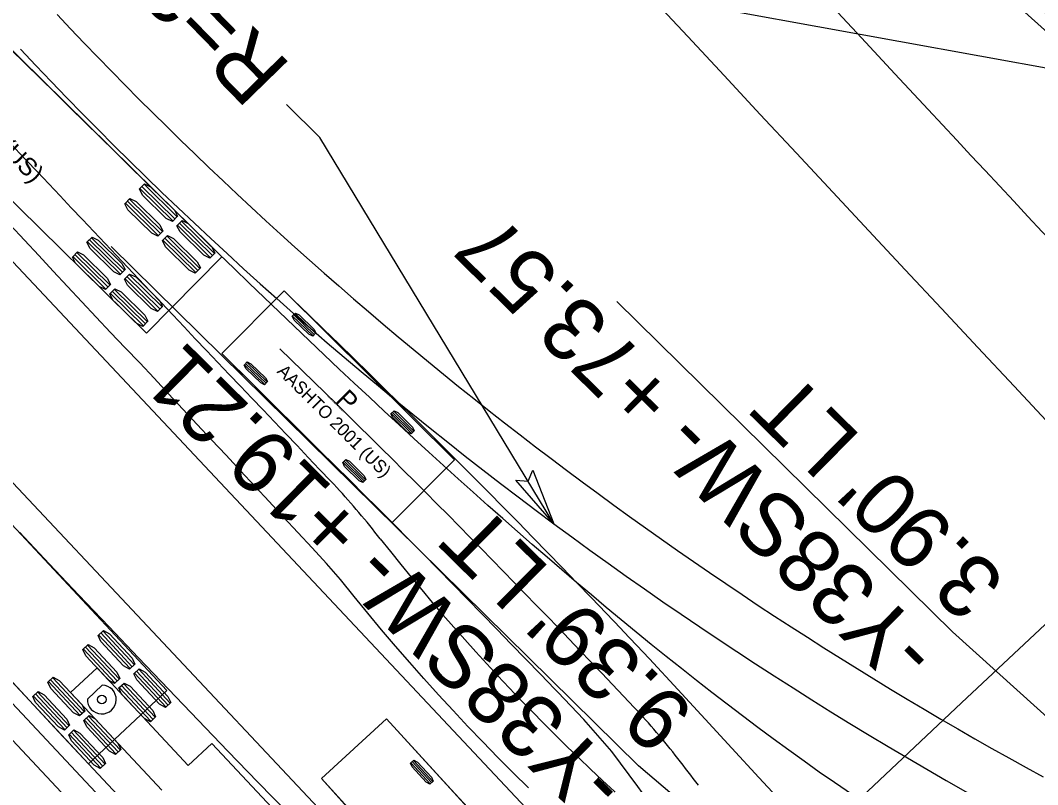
# Model space of a CAD drawing. Extents: x 1262642 to 1268358, y 767825 to 773481.
# Drawn here: x 1266608.5 to 1266689.1, y 772167.3 to 772227.9 of the extents above; entities that cross this region are included whole.
import ezdxf

# ---------------------------------------------------------------- set-up
doc = ezdxf.new("R2010")
doc.units = 0
for name, color, linetype in [('Prop Conc 2ft 6in Curb and Gutter', 7, 'Continuous'), ('Prop Conc 5in Monolithic Keyed In Island', 7, 'Continuous'), ('Prop Dimension', 7, 'Continuous'), ('Prop Dimension Text', 7, 'Continuous'), ('Prop EOT', 7, 'Continuous'), ('Prop Horizontal Alignment', 7, 'Continuous'), ('Prop Horizontal Alignment Station Label', 7, 'Continuous'), ('Prop Lane Lines', 7, 'Continuous'), ('Prop Paved Shoulder', 7, 'Continuous'), ('Prop Shade Light', 7, 'Continuous'), ('Prop Shade Medium', 7, 'Continuous'), ('Prop Terminator CELL', 7, 'Continuous'), ('Scratch_Level_3', 7, 'Continuous')]:
    doc.layers.add(name, color=color, linetype=linetype)

msp = doc.modelspace()

# ---------------------------------------------------------------- linework, layer by layer
at = {"layer": 'Prop Conc 2ft 6in Curb and Gutter'}
msp.add_line((1266506.171, 772278.961), (1266647.877, 772128.235), dxfattribs=at)
at = {"layer": 'Prop Conc 5in Monolithic Keyed In Island'}
for radius, start, end in [(11410.25, 222.8296601, 223.2792706), (11414.25, 222.8297896, 223.4298287)]:
    msp.add_arc((1275047.307, 780021.225), radius, start, end, dxfattribs=at)
at = {"layer": 'Prop Dimension'}
for p, q in [((1266650.81, 772187.946), (1266632.249, 772218.583)), ((1266731.744, 772134.821), (1266682.387, 772179.383)), ((1266684.313, 772146.162), (1266657.504, 772168.739))]:
    msp.add_line(p, q, dxfattribs=at)
at = {"layer": 'Prop Dimension Text'}
for p, q in [((1266755.582, 772212.148), (1266643.887, 772232.407)), ((1266632.249, 772218.583), (1266629.609, 772221.184)), ((1266657.52, 772168.758), (1266615.723, 772209.94)), ((1266682.387, 772179.383), (1266655.806, 772205.574))]:
    msp.add_line(p, q, dxfattribs=at)
at = {"layer": 'Prop EOT'}
msp.add_line((1266507.71, 772280.244), (1266649.334, 772129.605), dxfattribs=at)
for centre, radius, start, end in [((1275047.307, 780021.225), 11439, 220.5050908, 222.9935866), ((1275047.307, 780021.225), 11409.5, 222.8296601, 223.2792706), ((1275047.307, 780021.225), 11415, 222.8297896, 223.4298287), ((1266840.27, 772443.458), 318.091, 223.23333, 243.65317), ((1275047.307, 780021.225), 11439, 222.9935866, 223.2588472)]:
    msp.add_arc(centre, radius, start, end, dxfattribs=at)
at = {"layer": 'Prop Horizontal Alignment'}
msp.add_line((1266456.698, 772369.54), (1266660.642, 772152.615), dxfattribs=at)
at = {"layer": 'Prop Horizontal Alignment Station Label'}
for p, q in [((1266683.114, 772173.743), (1266860.999, 772340.982)), ((1266769.823, 772154.715), (1266566.881, 772338.064)), ((1266661.735, 772153.643), (1266683.114, 772173.743))]:
    msp.add_line(p, q, dxfattribs=at)
at = {"layer": 'Prop Lane Lines'}
msp.add_line((1266516.453, 772288.464), (1266651.899, 772144.396), dxfattribs=at)
for radius, start, end in [(11427, 216.3674993, 223.5476842), (11415, 220.9464115, 223.1041206)]:
    msp.add_arc((1275047.307, 780021.225), radius, start, end, dxfattribs=at)
at = {"layer": 'Prop Paved Shoulder'}
for centre, radius, start, end in [((1275047.307, 780021.225), 11449, 220.5050908, 223.2024475), ((1266840.27, 772443.458), 314.091, 223.23333, 241.33253)]:
    msp.add_arc(centre, radius, start, end, dxfattribs=at)
at = {"layer": 'Prop Shade Light'}
for centre, radius, start, end in [((1275047.307, 780021.225), 11439, 220.5050908, 222.9935866), ((1275047.307, 780021.225), 11449, 220.5050908, 223.2024475), ((1266840.27, 772443.458), 314.091, 223.23333, 241.33253), ((1266840.27, 772443.458), 318.091, 223.23333, 243.65317), ((1275047.307, 780021.225), 11439, 222.9935866, 223.2588472)]:
    msp.add_arc(centre, radius, start, end, dxfattribs=at)
at = {"layer": 'Prop Shade Medium'}
for radius, start, end in [(11410.25, 222.8296601, 223.2792706), (11414.25, 222.8297896, 223.4298287)]:
    msp.add_arc((1275047.307, 780021.225), radius, start, end, dxfattribs=at)
at = {"layer": 'Prop Terminator CELL'}
msp.add_lwpolyline([(1266649.141, 772192.197), (1266650.81, 772187.946), (1266647.781, 772191.402), (1266648.763, 772191.325)], close=True, dxfattribs=at)
at = {"layer": 'Scratch_Level_3'}
for p, q in [((1266624.483, 772209.122), (1266590.256, 772242.775)), ((1266584.297, 772236.714), (1266618.524, 772203.061)), ((1266618.321, 772214.86), (1266620.935, 772212.289)), ((1266617.999, 772214.533), (1266620.614, 772211.962)), ((1266618.16, 772214.696), (1266620.775, 772212.126)), ((1266616.843, 772213.357), (1266619.457, 772210.786)), ((1266617.003, 772213.52), (1266619.618, 772210.949)), ((1266617.164, 772213.683), (1266619.779, 772211.113)), ((1266620.971, 772211.612), (1266623.585, 772209.041)), ((1266621.131, 772211.775), (1266623.746, 772209.205)), ((1266621.292, 772211.939), (1266623.906, 772209.368)), ((1266620.135, 772210.762), (1266622.75, 772208.191)), ((1266613.84, 772210.302), (1266616.454, 772207.732)), ((1266614, 772210.466), (1266616.615, 772207.895)), ((1266614.161, 772210.629), (1266616.776, 772208.058)), ((1266619.814, 772210.435), (1266622.428, 772207.865)), ((1266619.974, 772210.599), (1266622.589, 772208.028)), ((1266620.129, 772174.722), (1266587.354, 772209.79)), ((1266612.683, 772209.126), (1266615.297, 772206.555)), ((1266612.843, 772209.289), (1266615.458, 772206.718)), ((1266613.004, 772209.452), (1266615.619, 772206.882)), ((1266618.524, 772203.061), (1266624.483, 772209.122)), ((1266616.971, 772207.544), (1266619.586, 772204.974)), ((1266617.132, 772207.708), (1266619.747, 772205.137)), ((1266616.811, 772207.381), (1266619.425, 772204.81)), ((1266615.654, 772206.204), (1266618.268, 772203.634)), ((1266615.815, 772206.368), (1266618.429, 772203.797)), ((1266615.975, 772206.531), (1266618.59, 772203.961)), ((1266629.43, 772206.402), (1266624.5, 772201.433)), ((1266642.918, 772193.02), (1266629.43, 772206.402)), ((1266630.101, 772204.418), (1266631.718, 772202.854)), ((1266630.199, 772204.519), (1266631.816, 772202.955)), ((1266630.296, 772204.62), (1266631.913, 772203.056)), ((1266581.144, 772203.986), (1266613.919, 772168.918)), ((1266624.5, 772201.433), (1266637.988, 772188.051)), ((1266624.5, 772201.433), (1266624.5, 772201.433)), ((1266626.276, 772200.553), (1266627.893, 772198.989)), ((1266626.374, 772200.654), (1266627.991, 772199.09)), ((1266626.472, 772200.755), (1266628.089, 772199.191)), ((1266637.921, 772196.679), (1266639.518, 772195.095)), ((1266638.02, 772196.779), (1266639.617, 772195.194)), ((1266638.119, 772196.879), (1266639.716, 772195.294)), ((1266634.289, 772193.019), (1266635.886, 772191.434)), ((1266637.988, 772188.051), (1266642.918, 772193.02)), ((1266634.091, 772192.819), (1266635.688, 772191.235)), ((1266634.19, 772192.919), (1266635.787, 772191.334)), ((1266617.392, 772176.612), (1266614.888, 772179.291)), ((1266617.559, 772176.769), (1266615.056, 772179.448)), ((1266617.225, 772176.456), (1266614.721, 772179.135)), ((1266616.019, 772175.329), (1266613.515, 772178.008)), ((1266616.187, 772175.486), (1266613.683, 772178.165)), ((1266616.354, 772175.642), (1266613.85, 772178.321)), ((1266614.6, 772176.512), (1266612.505, 772174.555)), ((1266621.826, 772168.78), (1266614.6, 772176.512)), ((1266620.07, 772173.412), (1266617.566, 772176.091)), ((1266620.237, 772173.568), (1266617.733, 772176.247)), ((1266620.405, 772173.725), (1266617.901, 772176.404)), ((1266613.255, 772172.746), (1266610.751, 772175.425)), ((1266613.422, 772172.902), (1266610.919, 772175.581)), ((1266613.59, 772173.059), (1266611.086, 772175.738)), ((1266619.199, 772172.598), (1266616.695, 772175.277)), ((1266612.217, 772171.776), (1266609.713, 772174.455)), ((1266612.384, 772171.932), (1266609.881, 772174.611)), ((1266612.505, 772174.555), (1266619.732, 772166.823)), ((1266615.014, 772175.154), (1266613.833, 772174.05)), ((1266613.919, 772168.918), (1266620.129, 772174.722)), ((1266618.864, 772172.285), (1266616.361, 772174.964)), ((1266619.032, 772172.442), (1266616.528, 772175.12)), ((1266620.129, 772174.722), (1266620.129, 772174.722)), ((1266612.05, 772171.619), (1266609.546, 772174.298)), ((1266616.1, 772169.702), (1266613.596, 772172.381)), ((1266616.268, 772169.858), (1266613.764, 772172.537)), ((1266616.435, 772170.015), (1266613.931, 772172.694)), ((1266637.54, 772172.472), (1266632.375, 772167.748)), ((1266650.364, 772158.453), (1266637.54, 772172.472)), ((1266614.895, 772168.575), (1266612.391, 772171.254)), ((1266615.062, 772168.732), (1266612.558, 772171.41)), ((1266615.229, 772168.888), (1266612.726, 772171.567)), ((1266623.701, 772170.533), (1266621.826, 772168.78)), ((1266633.944, 772159.574), (1266623.701, 772170.533)), ((1266640.994, 772167.331), (1266639.475, 772168.991)), ((1266641.098, 772167.426), (1266639.579, 772169.086)), ((1266641.201, 772167.521), (1266639.683, 772169.181)), ((1266632.375, 772167.748), (1266645.199, 772153.728))]:
    msp.add_line(p, q, dxfattribs=at)
for points in [[(1266673.036, 772167.425), (1266671.84, 772168.26), (1266670.632, 772169.117), (1266669.415, 772169.995), (1266668.189, 772170.89), (1266666.966, 772171.797), (1266665.748, 772172.713), (1266664.533, 772173.637), (1266663.323, 772174.57), (1266662.117, 772175.511), (1266660.915, 772176.46), (1266659.717, 772177.416), (1266658.523, 772178.379), (1266657.332, 772179.349), (1266656.146, 772180.326), (1266654.962, 772181.309), (1266653.783, 772182.298), (1266652.606, 772183.293), (1266651.433, 772184.293), (1266650.264, 772185.299), (1266649.096, 772186.311), (1266647.926, 772187.333), (1266646.754, 772188.364), (1266645.579, 772189.404), (1266644.404, 772190.453), (1266643.23, 772191.507), (1266642.057, 772192.567), (1266640.885, 772193.633), (1266639.714, 772194.703), (1266638.544, 772195.78), (1266637.366, 772196.869), (1266636.18, 772197.973), (1266634.986, 772199.09), (1266633.79, 772200.213), (1266632.596, 772201.341), (1266631.404, 772202.472), (1266630.213, 772203.607), (1266629.023, 772204.746), (1266627.836, 772205.888), (1266626.649, 772207.033), (1266625.465, 772208.181), (1266624.282, 772209.333), (1266623.1, 772210.487), (1266621.92, 772211.643), (1266620.741, 772212.802), (1266619.561, 772213.962), (1266618.381, 772215.122), (1266617.201, 772216.282), (1266616.021, 772217.443), (1266614.84, 772218.604), (1266613.658, 772219.766), (1266612.477, 772220.927), (1266611.295, 772222.089), (1266610.113, 772223.252), (1266608.93, 772224.414), (1266607.747, 772225.577)], [(1266648.799, 772167.005), (1266647.579, 772168.207), (1266646.37, 772169.42), (1266645.174, 772170.646), (1266643.99, 772171.883), (1266642.818, 772173.132), (1266641.658, 772174.392), (1266640.511, 772175.663), (1266639.377, 772176.946), (1266638.255, 772178.24), (1266637.145, 772179.545), (1266636.049, 772180.86), (1266634.966, 772182.187), (1266633.896, 772183.524), (1266632.792, 772184.803), (1266631.655, 772186.029), (1266630.52, 772187.252), (1266629.382, 772188.476), (1266628.241, 772189.701), (1266627.1, 772190.926), (1266625.96, 772192.149), (1266624.82, 772193.372), (1266623.68, 772194.594), (1266622.54, 772195.816), (1266621.4, 772197.037), (1266620.261, 772198.258), (1266619.121, 772199.478), (1266617.982, 772200.698), (1266616.815, 772201.884), (1266615.677, 772203.105), (1266614.539, 772204.325), (1266613.4, 772205.545), (1266612.262, 772206.764), (1266611.124, 772207.984), (1266609.985, 772209.203), (1266608.847, 772210.422), (1266607.709, 772211.641)], [(1266656.331, 772179.411), (1266656.1, 772179.653), (1266654.945, 772180.86), (1266653.787, 772182.066), (1266652.627, 772183.269), (1266651.464, 772184.47), (1266650.3, 772185.669), (1266649.133, 772186.866), (1266647.963, 772188.06), (1266646.792, 772189.252), (1266645.618, 772190.442), (1266644.442, 772191.63), (1266643.263, 772192.815), (1266642.083, 772193.998), (1266640.9, 772195.179), (1266639.715, 772196.358), (1266638.527, 772197.535), (1266637.338, 772198.709), (1266636.146, 772199.881), (1266634.952, 772201.051), (1266633.755, 772202.218), (1266632.557, 772203.383), (1266631.356, 772204.546), (1266630.153, 772205.707), (1266629.43, 772206.402)], [(1266651.109, 772174.581), (1266650.88, 772174.821), (1266649.734, 772176.019), (1266648.585, 772177.214), (1266647.433, 772178.408), (1266646.28, 772179.599), (1266645.124, 772180.788), (1266643.966, 772181.975), (1266642.806, 772183.159), (1266641.644, 772184.342), (1266640.479, 772185.522), (1266639.312, 772186.7), (1266638.143, 772187.876), (1266636.972, 772189.049), (1266635.798, 772190.221), (1266634.622, 772191.39), (1266633.445, 772192.557), (1266632.268, 772193.725), (1266631.091, 772194.893), (1266629.914, 772196.061), (1266628.737, 772197.229), (1266627.56, 772198.396), (1266626.383, 772199.564), (1266625.206, 772200.732), (1266624.5, 772201.433)], [(1266637.038, 772186.761), (1266636.832, 772187.023), (1266636.625, 772187.284), (1266636.417, 772187.544), (1266636.207, 772187.803), (1266635.996, 772188.062), (1266635.784, 772188.319), (1266635.571, 772188.575), (1266635.356, 772188.83), (1266635.14, 772189.084), (1266634.923, 772189.337), (1266634.705, 772189.589), (1266634.485, 772189.839), (1266634.264, 772190.088), (1266634.041, 772190.336), (1266633.817, 772190.583), (1266633.591, 772190.829), (1266633.364, 772191.073), (1266633.136, 772191.316)], [(1266608.453, 772187.273), (1266610.806, 772184.78), (1266613.162, 772182.289), (1266615.521, 772179.801), (1266617.883, 772177.316), (1266620.249, 772174.835), (1266622.61, 772172.365), (1266624.977, 772169.902), (1266627.354, 772167.447), (1266629.742, 772165.004), (1266632.147, 772162.577), (1266634.57, 772160.169), (1266634.57, 772160.169), (1266636.947, 772157.848), (1266639.345, 772155.55), (1266641.768, 772153.278), (1266644.215, 772151.034), (1266646.69, 772148.821), (1266649.193, 772146.639), (1266651.726, 772144.492), (1266652.236, 772144.067)], [(1266690.415, 772149.243), (1266689.004, 772149.965), (1266686.172, 772151.541), (1266683.438, 772153.233), (1266680.84, 772155.01), (1266678.327, 772156.902), (1266675.902, 772158.905), (1266673.571, 772161.016), (1266671.336, 772163.229), (1266669.179, 772165.518), (1266667.051, 772167.834), (1266664.917, 772170.144), (1266662.784, 772172.456), (1266660.62, 772174.808), (1266658.396, 772177.225), (1266656.331, 772179.411)], [(1266606.895, 772176.432), (1266609.236, 772173.927), (1266611.578, 772171.423), (1266613.919, 772168.918), (1266613.919, 772168.918), (1266616.254, 772166.424), (1266618.595, 772163.935), (1266620.942, 772161.452), (1266623.296, 772158.975), (1266625.654, 772156.502), (1266628.017, 772154.035), (1266628.017, 772154.035), (1266630.332, 772151.629), (1266632.653, 772149.229), (1266634.978, 772146.833), (1266637.309, 772144.443), (1266639.646, 772142.058), (1266641.987, 772139.677), (1266644.334, 772137.303), (1266644.804, 772136.829)], [(1266687.975, 772141.631), (1266686.422, 772142.419), (1266683.317, 772143.851), (1266680.261, 772145.436), (1266677.315, 772147.349), (1266674.459, 772149.405), (1266671.699, 772151.589), (1266669.041, 772153.896), (1266666.49, 772156.322), (1266664.052, 772158.861), (1266661.731, 772161.508), (1266659.532, 772164.257), (1266657.461, 772167.102), (1266655.408, 772169.89), (1266653.17, 772172.416), (1266651.109, 772174.581)], [(1266662.255, 772167.21), (1266662.055, 772167.477), (1266661.855, 772167.743), (1266661.654, 772168.009), (1266661.452, 772168.274), (1266661.249, 772168.539), (1266661.046, 772168.803), (1266660.841, 772169.066), (1266660.636, 772169.328), (1266660.429, 772169.59), (1266660.222, 772169.851), (1266660.013, 772170.111), (1266659.803, 772170.369), (1266659.592, 772170.627), (1266659.379, 772170.884), (1266659.165, 772171.14), (1266658.95, 772171.394), (1266658.733, 772171.647), (1266658.515, 772171.899), (1266658.295, 772172.15), (1266658.073, 772172.399), (1266657.85, 772172.647), (1266657.626, 772172.893), (1266657.399, 772173.138), (1266657.171, 772173.381)], [(1266637.54, 772172.472), (1266640.105, 772169.668), (1266642.673, 772166.867), (1266645.259, 772164.083), (1266647.865, 772161.318), (1266650.491, 772158.572), (1266650.491, 772158.572), (1266652.804, 772156.187), (1266655.131, 772153.817), (1266655.365, 772153.581)], [(1266632.375, 772167.748), (1266634.926, 772164.932), (1266637.493, 772162.129), (1266640.069, 772159.336), (1266642.634, 772156.532), (1266645.199, 772153.728), (1266645.199, 772153.728), (1266645.199, 772153.728), (1266647.522, 772151.304), (1266649.88, 772148.901), (1266650.117, 772148.661)], [(1266690.394, 772156.947), (1266688.288, 772158.04), (1266686.194, 772159.177), (1266684.124, 772160.351), (1266682.05, 772161.576), (1266679.914, 772162.886), (1266677.69, 772164.302), (1266675.393, 772165.817), (1266673.036, 772167.425)]]:
    msp.add_lwpolyline(points, dxfattribs=at)
for points in [[(1266617.96, 772214.493), (1266618.361, 772214.9), (1266618.847, 772214.663), (1266620.73, 772212.813), (1266620.975, 772212.33), (1266620.574, 772211.922), (1266620.087, 772212.159), (1266618.205, 772214.01)], [(1266616.803, 772213.316), (1266617.204, 772213.724), (1266617.691, 772213.487), (1266619.573, 772211.636), (1266619.818, 772211.153), (1266619.417, 772210.745), (1266618.93, 772210.982), (1266617.048, 772212.833)], [(1266620.931, 772211.571), (1266621.332, 772211.979), (1266621.819, 772211.742), (1266623.701, 772209.891), (1266623.946, 772209.409), (1266623.545, 772209.001), (1266623.058, 772209.238), (1266621.176, 772211.089)], [(1266619.774, 772210.395), (1266620.175, 772210.803), (1266620.662, 772210.566), (1266622.544, 772208.715), (1266622.789, 772208.232), (1266622.388, 772207.824), (1266621.902, 772208.061), (1266620.019, 772209.912)], [(1266613.8, 772210.262), (1266614.201, 772210.67), (1266614.688, 772210.433), (1266616.57, 772208.582), (1266616.815, 772208.099), (1266616.414, 772207.691), (1266615.927, 772207.928), (1266614.045, 772209.779)], [(1266612.643, 772209.085), (1266613.044, 772209.493), (1266613.531, 772209.256), (1266615.413, 772207.405), (1266615.659, 772206.922), (1266615.258, 772206.514), (1266614.771, 772206.751), (1266612.888, 772208.602)], [(1266616.771, 772207.34), (1266617.172, 772207.748), (1266617.659, 772207.511), (1266619.541, 772205.66), (1266619.786, 772205.178), (1266619.385, 772204.77), (1266618.899, 772205.007), (1266617.016, 772206.858)], [(1266615.614, 772206.164), (1266616.015, 772206.572), (1266616.502, 772206.335), (1266618.384, 772204.484), (1266618.63, 772204.001), (1266618.229, 772203.593), (1266617.742, 772203.83), (1266615.859, 772205.681)], [(1266630.076, 772204.393), (1266630.321, 772204.645), (1266630.62, 772204.502), (1266631.785, 772203.376), (1266631.938, 772203.081), (1266631.694, 772202.829), (1266631.394, 772202.972), (1266630.229, 772204.098)], [(1266626.252, 772200.528), (1266626.496, 772200.78), (1266626.796, 772200.637), (1266627.96, 772199.511), (1266628.113, 772199.216), (1266627.869, 772198.964), (1266627.569, 772199.107), (1266626.405, 772200.233)], [(1266637.896, 772196.655), (1266638.143, 772196.904), (1266638.441, 772196.757), (1266639.591, 772195.616), (1266639.741, 772195.319), (1266639.493, 772195.07), (1266639.195, 772195.217), (1266638.045, 772196.358)], [(1266634.066, 772192.795), (1266634.314, 772193.044), (1266634.612, 772192.897), (1266635.762, 772191.756), (1266635.911, 772191.459), (1266635.664, 772191.21), (1266635.365, 772191.357), (1266634.215, 772192.498)], [(1266617.601, 772176.808), (1266617.183, 772176.417), (1266616.707, 772176.674), (1266614.904, 772178.603), (1266614.679, 772179.096), (1266615.097, 772179.486), (1266615.574, 772179.229), (1266617.376, 772177.3)], [(1266616.395, 772175.681), (1266615.978, 772175.29), (1266615.501, 772175.548), (1266613.699, 772177.477), (1266613.474, 772177.969), (1266613.892, 772178.36), (1266614.368, 772178.102), (1266616.171, 772176.174)], [(1266620.446, 772173.763), (1266620.028, 772173.373), (1266619.552, 772173.63), (1266617.749, 772175.559), (1266617.524, 772176.052), (1266617.942, 772176.442), (1266618.419, 772176.185), (1266620.221, 772174.256)], [(1266613.631, 772173.098), (1266613.214, 772172.707), (1266612.737, 772172.964), (1266610.934, 772174.893), (1266610.71, 772175.386), (1266611.128, 772175.777), (1266611.604, 772175.519), (1266613.407, 772173.59)], [(1266619.241, 772172.637), (1266618.823, 772172.246), (1266618.346, 772172.504), (1266616.544, 772174.432), (1266616.319, 772174.925), (1266616.737, 772175.316), (1266617.213, 772175.058), (1266619.016, 772173.13)], [(1266612.426, 772171.971), (1266612.008, 772171.58), (1266611.532, 772171.838), (1266609.729, 772173.767), (1266609.504, 772174.259), (1266609.922, 772174.65), (1266610.399, 772174.393), (1266612.201, 772172.464)], [(1266616.476, 772170.054), (1266616.059, 772169.663), (1266615.582, 772169.92), (1266613.78, 772171.849), (1266613.555, 772172.342), (1266613.973, 772172.732), (1266614.449, 772172.475), (1266616.252, 772170.546)], [(1266615.271, 772168.927), (1266614.853, 772168.536), (1266614.377, 772168.794), (1266612.574, 772170.722), (1266612.349, 772171.215), (1266612.767, 772171.606), (1266613.244, 772171.348), (1266615.046, 772169.42)], [(1266641.227, 772167.544), (1266640.968, 772167.307), (1266640.677, 772167.468), (1266639.584, 772168.664), (1266639.449, 772168.967), (1266639.708, 772169.204), (1266639.999, 772169.043), (1266641.093, 772167.848)]]:
    msp.add_lwpolyline(points, close=True, dxfattribs=at)
msp.add_circle((1266614.975, 772174.011), 0.34, dxfattribs=at)
for centre, radius, start, end in [((1271970.399, 777276.391), 7371.864, 222.9672513, 223.6138945), ((1266020.322, 771572.394), 875.649, 43.340476, 45.954882), ((1266770.294, 772291.604), 169.556, 218.19483, 232.29011), ((1266614.975, 772174.011), 1.143, 178.06373, 88.06373)]:
    msp.add_arc(centre, radius, start, end, dxfattribs=at)

# ---------------------------------------------------------------- texts
at = {"layer": 'Prop Dimension'}
msp.add_text("R=318'", height=5, rotation=134.2575, dxfattribs=at).set_placement((1266630.079, 772224.229))
at = {"layer": 'Prop Dimension Text'}
for s, p in [('-Y38SW- +73.57', (1266681.506, 772178.123)), ('-Y38SW- +19.21', (1266656.856, 772167.656)), ("3.90' LT", (1266686.77, 772183.466)), ("9.39' LT", (1266662.12, 772172.998))]:
    msp.add_text(s, height=5, rotation=135.42387, dxfattribs=at).set_placement(p)
at = {"layer": 'Scratch_Level_3'}
for s, height, rotation, p in [('AASHTO 2001 (US)', 1.41667, 315.48486, (1266597.429, 772226.772)), ('AASHTO 2001 (US)', 1, 315.22493, (1266628.808, 772199.969)), ('P', 1.5, 315.22493, (1266633.439, 772197.664)), ('(c) 2016 Transoft Solutions, Inc. All rights reserved.', 0.06, 315.22493, (1266632.82, 772198.066))]:
    msp.add_text(s, height=height, rotation=rotation, dxfattribs=at).set_placement(p)

doc.saveas('drawing.dxf')
